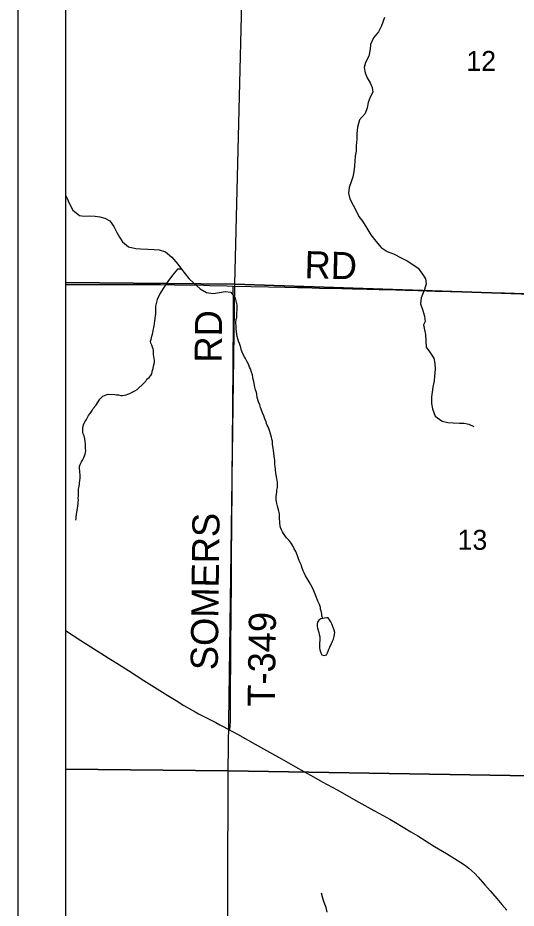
# Model space of a CAD drawing. Extents: x 0 to 34, y 0 to 22.
# Drawn here: x 2 to 3.044, y 15.009 to 16.874 of the extents above; entities that cross this region are included whole.
import ezdxf

# ---------------------------------------------------------------- set-up
doc = ezdxf.new("R2010")
doc.units = 0
for name, color, linetype in [('GM_X_Corporation', 7, 'Continuous'), ('GM_X_County_Road', 7, 'Continuous'), ('GM_X_County_Road_Text', 7, 'Continuous'), ('GM_X_Minor_Lake', 7, 'Continuous'), ('GM_X_Minor_River', 7, 'Continuous'), ('GM_X_Section_Text', 7, 'Continuous'), ('GM_X_Township_Road', 7, 'Continuous'), ('GM_X_Township_Road_Text', 7, 'Continuous'), ('SH_Data', 7, 'Continuous')]:
    doc.layers.add(name, color=color, linetype=linetype)

msp = doc.modelspace()

# ---------------------------------------------------------------- linework, layer by layer
at = {"layer": 'GM_X_Corporation'}
msp.add_lwpolyline([(2.1, 18.3932), (2.1, 14.1), (3.4463, 14.1), (3.448, 14.3179), (3.4516, 14.7743), (3.4533, 15.0461), (3.4601, 16.0804), (3.4672, 16.2781), (3.4754, 17.1134)], dxfattribs=at)
for points in [[(2.1, 17.3057), (2.1, 16.3195), (2.4544, 16.3158), (2.4791, 17.2994)], [(3.4847, 17.2912), (3.4681, 16.2816), (2.4544, 16.3158), (2.4791, 17.2994)], [(2.1, 16.3195), (2.1, 15.3004), (2.4405, 15.2964), (2.4544, 16.3158)], [(2.4544, 16.3158), (3.4681, 16.2816), (3.4534, 15.28), (2.4405, 15.2964)], [(2.1, 15.3004), (2.1, 14.2873), (2.4377, 14.2835), (2.4405, 15.2964)], [(2.4405, 15.2964), (3.4534, 15.28), (3.4532, 15.1884), (3.4477, 14.2699), (2.4377, 14.2835)]]:
    msp.add_lwpolyline(points, close=True, dxfattribs=at)
at = {"layer": 'GM_X_County_Road'}
for points in [[(2.1, 16.3152), (2.1199, 16.3151), (2.1466, 16.315), (2.182, 16.3152), (2.2198, 16.315), (2.2447, 16.3151), (2.2701, 16.315), (2.2835, 16.3152), (2.2987, 16.3151), (2.3284, 16.3148), (2.3899, 16.3138), (2.4017, 16.3134), (2.4384, 16.3122), (2.451, 16.3119), (2.4887, 16.3112), (2.5253, 16.3105), (2.5595, 16.3097), (2.5862, 16.3091), (2.6011, 16.3089), (2.6321, 16.3078), (2.6787, 16.3067), (2.7011, 16.3062), (2.7315, 16.3055), (2.757, 16.3047), (2.7918, 16.3038), (2.8104, 16.3034), (2.8383, 16.3026), (2.8569, 16.302), (2.8743, 16.3015), (2.8973, 16.3009), (2.9066, 16.3006), (2.9321, 16.3001), (2.9786, 16.2986), (3.0196, 16.2974), (3.0619, 16.2965)], [(2.1, 15.5903), (2.132, 15.57), (2.153, 15.5567), (2.1892, 15.5337), (2.2127, 15.5186), (2.2316, 15.5067), (2.2642, 15.4862), (2.3142, 15.4548), (2.3316, 15.4439), (2.348, 15.4338), (2.3651, 15.4238), (2.3716, 15.4202), (2.3787, 15.4163), (2.3941, 15.4083), (2.4024, 15.4041), (2.4145, 15.3978), (2.4233, 15.3932), (2.4316, 15.3889), (2.4443, 15.3821), (2.447, 15.3807), (2.46, 15.3735), (2.4975, 15.3526), (2.5213, 15.3391), (2.5522, 15.3218), (2.5771, 15.3078), (2.6042, 15.2926), (2.6145, 15.2869), (2.6378, 15.2739), (2.6688, 15.2568), (2.7144, 15.2313), (2.7459, 15.2139), (2.7563, 15.2082), (2.7791, 15.1956), (2.791, 15.1888), (2.8234, 15.1691), (2.8377, 15.1603), (2.8732, 15.1386), (2.8981, 15.1234), (2.9151, 15.113), (2.9277, 15.105), (2.9375, 15.0983), (2.945, 15.0927), (2.9512, 15.0875), (2.9571, 15.0819), (2.9643, 15.0741), (2.9786, 15.0578), (2.9892, 15.0456), (3.0035, 15.0291), (3.014, 15.0169), (3.0241, 15.0051)]]:
    msp.add_lwpolyline(points, dxfattribs=at)
at = {"layer": 'GM_X_Minor_Lake'}
for points in [[(2.6504, 15.6168), (2.6472, 15.6172), (2.6426, 15.6165), (2.6388, 15.6159), (2.635, 15.6149), (2.6304, 15.6123), (2.628, 15.6082), (2.6271, 15.6037), (2.627, 15.5995), (2.6276, 15.5953), (2.6304, 15.5861), (2.6314, 15.5823), (2.6324, 15.5773), (2.6327, 15.5731), (2.6326, 15.5693), (2.6321, 15.5655), (2.6318, 15.5545), (2.6328, 15.5499), (2.6345, 15.5438), (2.637, 15.5399), (2.6415, 15.5383), (2.6465, 15.5397), (2.6485, 15.5438), (2.6498, 15.5476), (2.6518, 15.5517), (2.6534, 15.5558), (2.6574, 15.5633), (2.6595, 15.5682), (2.6611, 15.5727), (2.6628, 15.578), (2.6637, 15.5829), (2.6638, 15.5867), (2.6625, 15.5911), (2.6587, 15.6024)], [(2.6587, 15.6024), (2.6575, 15.6047), (2.6557, 15.609), (2.6532, 15.6132), (2.6504, 15.6168)]]:
    msp.add_lwpolyline(points, dxfattribs=at)
at = {"layer": 'GM_X_Minor_River'}
for points in [[(2.7678, 16.8743), (2.762, 16.857), (2.7553, 16.8443), (2.7451, 16.8316), (2.7391, 16.8178), (2.7384, 16.8083), (2.7354, 16.7932), (2.7286, 16.7801), (2.7253, 16.7699), (2.7273, 16.7581), (2.732, 16.7481), (2.7382, 16.7377), (2.7425, 16.7278), (2.7438, 16.7179), (2.7378, 16.7078), (2.7341, 16.6965), (2.732, 16.6852), (2.7275, 16.6735), (2.7158, 16.6598), (2.7116, 16.6447), (2.7101, 16.6315), (2.7102, 16.6193), (2.7091, 16.6053), (2.7085, 16.5944), (2.7067, 16.5838), (2.7061, 16.5743)], [(2.7061, 16.5743), (2.7054, 16.5633), (2.7036, 16.5512), (2.7018, 16.5407), (2.6981, 16.5305), (2.6944, 16.5181), (2.693, 16.5067), (2.6954, 16.4946), (2.7022, 16.4811), (2.708, 16.4707), (2.7145, 16.4577), (2.7219, 16.4476), (2.7314, 16.4334), (2.7394, 16.4191), (2.75, 16.4056), (2.7615, 16.3928), (2.7734, 16.3846), (2.7873, 16.3793), (2.8045, 16.3705), (2.8158, 16.3649), (2.8255, 16.3586), (2.8389, 16.3496), (2.8477, 16.3365), (2.8539, 16.3268), (2.8555, 16.3169), (2.8522, 16.3045), (2.845, 16.2876), (2.8435, 16.2744), (2.8474, 16.2625), (2.852, 16.2491), (2.8532, 16.2377)], [(2.1, 16.502), (2.1037, 16.4954), (2.1076, 16.4854), (2.1152, 16.4708), (2.129, 16.4599), (2.1388, 16.4585), (2.1494, 16.459), (2.1619, 16.4583), (2.1717, 16.4569), (2.1823, 16.454), (2.1928, 16.4488), (2.2012, 16.4365), (2.2077, 16.4242), (2.2132, 16.4146), (2.2194, 16.4046), (2.232, 16.394), (2.2471, 16.3906), (2.2569, 16.39), (2.2725, 16.3892), (2.2857, 16.3882), (2.2959, 16.3875), (2.3095, 16.3838), (2.3229, 16.3721), (2.3354, 16.3581), (2.3427, 16.3473), (2.3505, 16.3376), (2.3586, 16.328), (2.3689, 16.3178), (2.3819, 16.3058), (2.3954, 16.2982), (2.4082, 16.2964), (2.4223, 16.2987), (2.4341, 16.3007), (2.4462, 16.2989), (2.455, 16.2865), (2.4588, 16.2728), (2.4578, 16.2445)], [(2.3427, 16.3473), (2.3344, 16.3471), (2.3242, 16.3345), (2.314, 16.3215), (2.3061, 16.3088), (2.2982, 16.2968), (2.2918, 16.2837), (2.2885, 16.2698), (2.2884, 16.2516)], [(2.287, 16.2395), (2.2874, 16.2432), (2.2884, 16.2516)], [(2.4749, 16.1639), (2.4717, 16.1697), (2.4681, 16.1789), (2.4671, 16.1835), (2.4657, 16.1873), (2.4643, 16.1919), (2.4622, 16.1965), (2.4608, 16.2011), (2.4594, 16.2065), (2.4588, 16.2111), (2.4578, 16.2164), (2.4576, 16.2225), (2.4577, 16.2259), (2.4574, 16.2293), (2.4568, 16.2335), (2.4569, 16.2373), (2.4574, 16.2411), (2.4578, 16.2445)], [(2.1218, 15.8216), (2.1223, 15.8254), (2.1224, 15.8288), (2.1233, 15.8337), (2.1238, 15.8382), (2.1243, 15.8416), (2.1248, 15.8466), (2.1257, 15.8511), (2.1262, 15.856), (2.1267, 15.8594), (2.1268, 15.8636), (2.1265, 15.8678), (2.1271, 15.8731), (2.1273, 15.883), (2.1274, 15.8864), (2.1284, 15.8921), (2.1299, 15.9057), (2.1304, 15.9091), (2.1306, 15.9175), (2.13, 15.9217), (2.1297, 15.9251), (2.1294, 15.9293), (2.1295, 15.9338), (2.1308, 15.9384), (2.1332, 15.9436), (2.1356, 15.9473), (2.1381, 15.953), (2.1397, 15.9567), (2.1409, 15.9601), (2.1418, 15.9635), (2.1423, 15.9677), (2.142, 15.9719), (2.1415, 15.9817), (2.1413, 15.9859), (2.1403, 15.9917), (2.139, 15.9982), (2.1372, 16.0024), (2.1365, 16.0058), (2.1359, 16.01), (2.136, 16.0146), (2.1369, 16.0191), (2.1385, 16.0236), (2.1413, 16.0281), (2.1437, 16.0322), (2.1453, 16.0356), (2.1481, 16.0408), (2.1513, 16.0453), (2.1556, 16.0513), (2.1577, 16.0558), (2.1632, 16.0617), (2.1715, 16.0748), (2.1746, 16.0781), (2.1781, 16.081), (2.1816, 16.0828), (2.1854, 16.0842), (2.1892, 16.0853), (2.2033, 16.0849), (2.2067, 16.0844), (2.2108, 16.0839), (2.2157, 16.083), (2.2191, 16.0829), (2.223, 16.0832), (2.2268, 16.0842), (2.2302, 16.0853), (2.2348, 16.087), (2.2394, 16.0896), (2.2452, 16.0928), (2.2502, 16.0953), (2.2643, 16.1086), (2.2682, 16.1127), (2.2706, 16.1168), (2.2749, 16.1205), (2.2784, 16.1249), (2.2808, 16.1283), (2.2825, 16.1358), (2.2834, 16.1392), (2.2846, 16.1445), (2.2855, 16.1491), (2.286, 16.1528), (2.2861, 16.1563), (2.2859, 16.1605), (2.2848, 16.1647), (2.2846, 16.1685), (2.2843, 16.1719), (2.284, 16.1765), (2.2834, 16.1807), (2.282, 16.1841), (2.281, 16.1883), (2.2788, 16.1922), (2.2781, 16.1964), (2.2794, 16.2001), (2.2802, 16.2035), (2.2811, 16.2073), (2.2824, 16.2115), (2.2828, 16.2149), (2.2837, 16.2183), (2.2842, 16.2221), (2.285, 16.2254), (2.2855, 16.2289), (2.286, 16.2326), (2.287, 16.2395)], [(2.8532, 16.2377), (2.8498, 16.2308), (2.8518, 16.2205), (2.8542, 16.2106), (2.8549, 16.1973), (2.8553, 16.184), (2.8629, 16.1735), (2.8713, 16.1607), (2.8736, 16.1496), (2.874, 16.1382), (2.8732, 16.123), (2.8725, 16.1136), (2.8691, 16.1), (2.868, 16.0898), (2.8666, 16.0799), (2.8669, 16.0663), (2.8688, 16.0548), (2.8741, 16.0395), (2.8886, 16.0288), (2.901, 16.0261), (2.912, 16.0258), (2.9249, 16.025), (2.9351, 16.0251), (2.9449, 16.0229), (2.955, 16.0181)], [(2.6388, 15.6159), (2.6371, 15.6216), (2.6368, 15.6251), (2.6355, 15.6319), (2.6344, 15.6354), (2.6338, 15.6388), (2.6317, 15.645), (2.6288, 15.6523), (2.6256, 15.66), (2.6228, 15.6665), (2.6203, 15.6734), (2.6171, 15.68), (2.6139, 15.6861), (2.6103, 15.6927), (2.6063, 15.6993), (2.603, 15.7051), (2.6002, 15.7112), (2.5976, 15.7158), (2.5952, 15.7235), (2.5942, 15.727), (2.5917, 15.7324), (2.5881, 15.7408), (2.5853, 15.7489), (2.5821, 15.7558), (2.5792, 15.7616), (2.576, 15.7678), (2.5723, 15.7736), (2.5683, 15.7794), (2.5632, 15.7848), (2.5595, 15.7895), (2.5566, 15.7934), (2.5544, 15.7972), (2.5526, 15.8015), (2.5505, 15.8061), (2.5498, 15.8099), (2.5489, 15.8153), (2.5486, 15.8194), (2.5483, 15.8229), (2.5481, 15.8297), (2.5479, 15.835), (2.5469, 15.8404), (2.5442, 15.8511), (2.5428, 15.8568), (2.5418, 15.861), (2.5415, 15.8645), (2.5413, 15.8702), (2.5419, 15.877), (2.5424, 15.8804), (2.5428, 15.8842), (2.5438, 15.8902), (2.5439, 15.8956), (2.5437, 15.9013), (2.5434, 15.9051), (2.5428, 15.9085), (2.5421, 15.9131), (2.5408, 15.9196), (2.5396, 15.9287), (2.5389, 15.9337), (2.5383, 15.9383), (2.5384, 15.9428), (2.5382, 15.9474), (2.5369, 15.955), (2.536, 15.963), (2.5353, 15.9669), (2.5347, 15.9722), (2.5334, 15.9802), (2.5332, 15.9871), (2.5322, 15.9916), (2.5316, 15.9958), (2.5295, 16.0024), (2.527, 16.0093), (2.5242, 16.0169), (2.5224, 16.0204), (2.521, 16.0239), (2.52, 16.0273), (2.5175, 16.0339), (2.5154, 16.04), (2.5129, 16.0465), (2.5115, 16.05), (2.5101, 16.0538), (2.5087, 16.0573), (2.5069, 16.063), (2.5045, 16.0696), (2.5017, 16.0788), (2.5004, 16.0853), (2.4997, 16.0891), (2.4976, 16.0945), (2.4966, 16.1002), (2.496, 16.1036), (2.4953, 16.1086), (2.4943, 16.112), (2.4933, 16.117), (2.4926, 16.1204), (2.4913, 16.1258), (2.4892, 16.1315), (2.4871, 16.1384), (2.4853, 16.1423), (2.4832, 16.1481), (2.4807, 16.1534), (2.4771, 16.1604), (2.4749, 16.1639)], [(2.6479, 15.0008), (2.646, 15.0103), (2.6421, 15.0207), (2.639, 15.0303), (2.6362, 15.0402)]]:
    msp.add_lwpolyline(points, dxfattribs=at)
at = {"layer": 'GM_X_Township_Road'}
msp.add_lwpolyline([(2.4443, 15.3821), (2.4449, 15.3914), (2.4454, 15.4001), (2.4456, 15.4138), (2.4458, 15.4386), (2.4458, 15.4889), (2.446, 15.5069), (2.4462, 15.5243), (2.4463, 15.5442), (2.4464, 15.561), (2.4465, 15.5821), (2.4467, 15.5989), (2.4469, 15.633), (2.4473, 15.6846), (2.4474, 15.6951), (2.4474, 15.7094), (2.4476, 15.7411), (2.4478, 15.7647), (2.448, 15.7914), (2.4482, 15.8106), (2.4483, 15.8373), (2.4487, 15.8659), (2.4488, 15.8783), (2.4492, 15.9237), (2.4498, 15.969), (2.45, 16.0063), (2.4502, 16.0355), (2.4504, 16.0603), (2.4505, 16.0796), (2.4509, 16.1299), (2.4509, 16.1367), (2.4509, 16.156), (2.451, 16.1715), (2.4515, 16.2187), (2.4517, 16.2392), (2.4516, 16.2674), (2.4515, 16.2848), (2.4511, 16.3022), (2.451, 16.3119)], dxfattribs=at)
at = {"layer": 'SH_Data'}
for p, q in [((2, 21), (2, 14)), ((2.1, 20.9), (2.1, 14.1)), ((2.1, 20.9), (2.1, 14.1)), ((2.1, 20.9), (2.1, 14.1))]:
    msp.add_line(p, q, dxfattribs=at)

# ---------------------------------------------------------------- texts
at = {"layer": 'GM_X_County_Road_Text'}
msp.add_text('RD', height=0.05682, rotation=358.5184, dxfattribs=at).set_placement((2.6001, 16.3285))
at = {"layer": 'GM_X_Section_Text'}
for s, p in [('12', (2.9395, 16.7624)), ('13', (2.9212, 15.7596))]:
    msp.add_text(s, height=0.04186, rotation=0, dxfattribs=at).set_placement(p)
at = {"layer": 'GM_X_Township_Road_Text'}
for s, rotation, p in [('RD', 89.5059, (2.4272, 16.1514)), ('SOMERS', 89.3118, (2.4188, 15.5073)), ('T-349', 89.1574, (2.5381, 15.4306))]:
    msp.add_text(s, height=0.05682, rotation=rotation, dxfattribs=at).set_placement(p)

doc.saveas('drawing.dxf')
